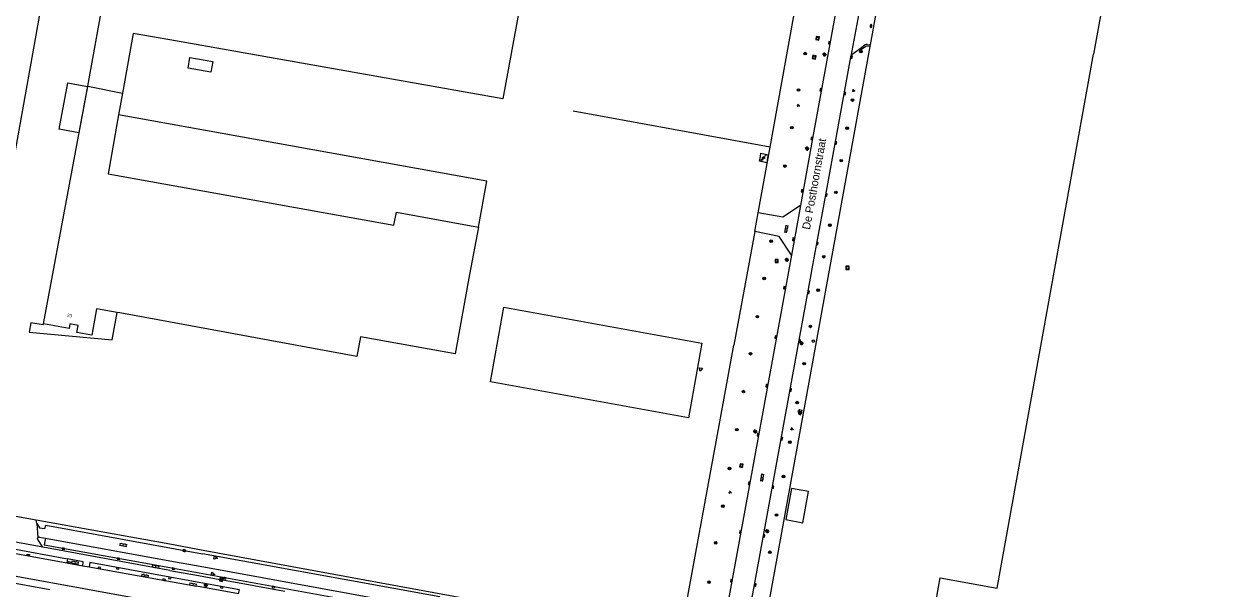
# Model space of a CAD drawing. Extents: x 130998 to 133001, y 398999 to 403002.
# Drawn here: x 131954.5 to 132332.6, y 399638.5 to 399814.9 of the extents above; entities that cross this region are included whole.
import ezdxf

# ---------------------------------------------------------------- set-up
doc = ezdxf.new("R2010")
doc.units = 0
for name, color, linetype in [('gg-afsc-hekwerk', 7, 'Continuous'), ('gg-anno-huisnummerreeks BGT', 7, 'Continuous'), ('gg-anno-openbare ruimte label', 7, 'Continuous'), ('gg-bbg-gedigitaliseerde bebouwing', 7, 'Continuous'), ('gg-bbg-gedigitaliseerde bijgebouw', 7, 'Continuous'), ('gg-bbg-hoofdgebouw', 7, 'Continuous'), ('gg-bbg-lage trafo', 7, 'Continuous'), ('gg-bbg-luifel en loopbrug', 7, 'Continuous'), ('gg-bbg-tussenscheiding', 7, 'Continuous'), ('gg-knt-verharding', 7, 'Continuous'), ('gg-knt-verharding nz', 7, 'Continuous'), ('gt-grn-weggrens', 7, 'Continuous'), ('gt-symb-boom', 7, 'Continuous'), ('gt-symb-brandkraan', 7, 'Continuous'), ('gt-symb-groenvak', 7, 'Continuous'), ('gt-symb-klinker verharding', 7, 'Continuous'), ('gt-symb-kolk', 7, 'Continuous'), ('gt-symb-kolk center center', 7, 'Continuous'), ('gt-symb-lichtmast', 7, 'Continuous'), ('gt-symb-rioolschacht', 7, 'Continuous'), ('gt-symb-trafo symbool', 7, 'Continuous'), ('gt-symb-waterafsluiter', 7, 'Continuous')]:
    doc.layers.add(name, color=color, linetype=linetype)

# ---------------------------------------------------------------- blocks, each defined once
blk = doc.blocks.new('gt0-BR')
at = {"layer": 'gt-symb-brandkraan'}
for centre, radius, start, end in [((-0.24, 0), 0.206, 107.5669, 252.4331), ((0.6, -2.66), 3, 106.892, 107.5669), ((0, -0.69), 0.938, 73.108, 106.892), ((-0.6, -2.66), 3, 72.4331, 73.108), ((0.24, 0), 0.206, 287.567, 72.4331), ((0.6, 2.66), 3, 252.4331, 253.108), ((0, 0.69), 0.938, 253.108, 286.8921), ((-0.6, 2.66), 3, 286.8921, 287.567)]:
    blk.add_arc(centre, radius, start, end, dxfattribs=at)
blk = doc.blocks.new('gt0-RS')
at = {"layer": 'gt-symb-rioolschacht'}
blk.add_lwpolyline([(-0.5, -0.5), (0.5, -0.5), (0.5, 0.5), (-0.5, 0.5)], close=True, dxfattribs=at)
blk.add_circle((0, 0), 0.375, dxfattribs=at)
blk = doc.blocks.new('gt0-BOOM')
at = {"layer": 'gt-symb-boom'}
for radius in [0.4, 0.2]:
    blk.add_circle((0, 0), radius, dxfattribs=at)
blk = doc.blocks.new('gt0-KOLK')
at = {"layer": 'gt-symb-kolk'}
blk.add_lwpolyline([(0, 0), (0.37, 0), (0.37, 0.4), (-0.38, 0.4), (-0.38, 0), (0, 0)], dxfattribs=at)
blk = doc.blocks.new('gt0-GRVAK')
at = {"layer": 'gt-symb-groenvak'}
for p, q in [((-0.11, 0.19), (-0.23, 0.24)), ((-0.18, 0.15), (0.09, 0.15)), ((-0.09, 0.21), (-0.16, 0.32)), ((-0.05, 0.21), (-0.05, 0.39)), ((0, 0.21), (0.06, 0.32)), ((0.01, 0.19), (0.13, 0.24)), ((0.26, -0.05), (0.2, 0.06)), ((0.3, -0.05), (0.3, 0.13)), ((0.35, -0.05), (0.41, 0.06)), ((-0.24, -0.23), (-0.36, -0.18)), ((-0.32, -0.26), (-0.05, -0.26)), ((-0.23, -0.21), (-0.29, -0.09)), ((-0.18, -0.2), (-0.18, -0.02)), ((-0.14, -0.21), (-0.07, -0.09)), ((-0.12, -0.23), (0, -0.18)), ((0.24, -0.07), (0.12, -0.02)), ((0.17, -0.11), (0.44, -0.11)), ((0.37, -0.07), (0.49, -0.02))]:
    blk.add_line(p, q, dxfattribs=at)
blk = doc.blocks.new('gt0-LMAST')
at = {"layer": 'gt-symb-lichtmast'}
for p, q in [((-0.18, 0.17), (-0.45, 0.44)), ((-0.01, 0.25), (-0.01, 0.62)), ((0.17, 0.17), (0.44, 0.44)), ((-0.26, 0), (-0.63, 0)), ((-0.18, -0.18), (-0.45, -0.45)), ((-0.01, -0.25), (-0.01, -0.63)), ((0.44, -0.45), (0.17, -0.18)), ((0.24, 0), (0.62, 0))]:
    blk.add_line(p, q, dxfattribs=at)
blk.add_circle((-0.01, 0), 0.25, dxfattribs=at)
blk = doc.blocks.new('gt0-KL1')
at = {"layer": 'gt-symb-klinker verharding'}
for p, q in [((-1.15, 0.3), (1.15, 0.3)), ((-1, -0.3), (-1, 0.3)), ((-0.5, 0.3), (-0.5, 0.45)), ((0, -0.3), (0, 0.3)), ((0.5, 0.3), (0.5, 0.45)), ((1, -0.3), (1, 0.3)), ((-1.15, -0.3), (1.15, -0.3)), ((-0.5, -0.45), (-0.5, -0.3)), ((0.5, -0.45), (0.5, -0.3))]:
    blk.add_line(p, q, dxfattribs=at)
blk = doc.blocks.new('gt0-HSP')
at = {"layer": 'gt-symb-trafo symbool'}
for points in [[(0.77, 0.75), (-0.53, 0), (0.47, 0), (-0.83, -0.75)], [(-0.22, -0.24), (-0.83, -0.75), (-0.08, -0.48)]]:
    blk.add_lwpolyline(points, dxfattribs=at)
blk = doc.blocks.new('gt0-WAFSL')
at = {"layer": 'gt-symb-waterafsluiter'}
for p, q in [((-0.5, -0.33), (0, 0.67)), ((0, 0.67), (0.5, -0.33)), ((0.5, -0.33), (-0.5, -0.33))]:
    blk.add_line(p, q, dxfattribs=at)
blk = doc.blocks.new('gt0-KOLKCC')
at = {"layer": 'gt-symb-kolk center center'}
blk.add_lwpolyline([(-0.38, 0.2), (0.38, 0.2), (0.38, -0.2), (-0.38, -0.2)], close=True, dxfattribs=at)

msp = doc.modelspace()

# ---------------------------------------------------------------- linework, layer by layer
at = {"layer": 'gg-afsc-hekwerk'}
for p, q in [((132187.47, 399776.47), (132196.35, 399825.7)), ((132220.46, 399818.27), (132218.65, 399808.43)), ((132218.65, 399808.43), (132218.55, 399807.89)), ((132187.47, 399776.47), (132125.97, 399787.71)), ((132183.73, 399756.01), (132187.47, 399776.47)), ((132182.65, 399750.15), (132183.73, 399756.01)), ((132182.65, 399750.15), (132176.15, 399714.67)), ((131958.19, 399660.02), (131943.8, 399662.62)), ((132000, 399652.44), (131958.19, 399660.02)), ((132010.38, 399650.54), (132000, 399652.44)), ((132159.36, 399623.22), (132010.38, 399650.54))]:
    msp.add_line(p, q, dxfattribs=at)
for points in [[(132218.55, 399807.89), (132187.28, 399635.5), (132187.07, 399633.45), (132186.62, 399631.09)], [(132159.36, 399623.22), (132171.78, 399690.65), (132176.15, 399714.67)]]:
    msp.add_lwpolyline(points, dxfattribs=at)
at = {"layer": 'gg-bbg-gedigitaliseerde bebouwing'}
for p, q in [((131974.33, 399795.51), (131987.77, 399870.1)), ((131960.49, 399721.28), (131974.33, 399795.51)), ((131985.19, 399793.41), (131983.98, 399786.64)), ((132096.35, 399751.54), (132093.54, 399736.72)), ((132093.54, 399736.72), (132089.03, 399711.94))]:
    msp.add_line(p, q, dxfattribs=at)
for points in [[(132114.18, 399847.19), (132103.99, 399791.64), (132000, 399810.02)], [(132000, 399810.02), (131988.52, 399812.05), (131985.19, 399793.41)], [(131983.98, 399786.64), (131980.67, 399768.12), (132069.97, 399752.08)], [(132069.97, 399752.08), (132070.78, 399756.15), (132096.35, 399751.54)]]:
    msp.add_lwpolyline(points, dxfattribs=at)
at = {"layer": 'gg-bbg-gedigitaliseerde bijgebouw'}
msp.add_lwpolyline([(132012.79, 399799.93), (132005.68, 399801.19), (132006.26, 399804.5), (132013.38, 399803.25), (132012.79, 399799.93)], dxfattribs=at)
at = {"layer": 'gg-bbg-hoofdgebouw'}
msp.add_line((131959.72, 399820.2), (131946.23, 399745.68), dxfattribs=at)
for points in [[(132454.05, 399775.54), (132469.16, 399858.93), (132303.58, 399888.86), (132288.47, 399805.5)], [(132454.05, 399775.54), (132418.41, 399578.69), (132399.92, 399582.07), (132402.13, 399594.22), (132402.06, 399594.24), (132402.06, 399594.26), (132250.49, 399621.7), (132250.45, 399621.52), (132249.94, 399621.63), (132249.86, 399621.77), (132237.31, 399623.98), (132240.58, 399641.99), (132258.31, 399638.73), (132288.47, 399805.5)], [(131983.49, 399724.86), (131977.08, 399726.04), (131975.62, 399717.77), (131970.96, 399718.6), (131971.36, 399720.82), (131968.76, 399721.28), (131968.51, 399719.86), (131960.49, 399721.28)], [(132089.03, 399711.94), (132059.49, 399717.29), (132058.35, 399711.11), (131984.32, 399724.71), (131983.49, 399724.86)], [(132166.16, 399715.24), (132161.91, 399691.91), (132100.06, 399703.16), (132104.31, 399726.49), (132166.16, 399715.24)]]:
    msp.add_lwpolyline(points, dxfattribs=at)
at = {"layer": 'gg-bbg-lage trafo'}
msp.add_lwpolyline([(132184.1, 399772.07), (132184.45, 399773.55), (132184.56, 399774.57), (132186.87, 399774.11), (132186.6, 399773.14), (132186.37, 399771.6), (132184.1, 399772.07)], dxfattribs=at)
at = {"layer": 'gg-bbg-luifel en loopbrug'}
for points in [[(131965.41, 399782.13), (131968.11, 399796.61), (131974.21, 399795.47), (131971.51, 399780.99), (131965.41, 399782.13)], [(132096.35, 399751.54), (132098.94, 399765.84), (131983.98, 399786.64)], [(131960.49, 399721.28), (131960.43, 399720.95), (131956.52, 399721.65), (131955.98, 399718.66), (131981.98, 399716.28), (131983.49, 399724.86)], [(132194.08, 399669.87), (132192.32, 399660.16), (132197.69, 399659.18), (132199.45, 399668.9), (132194.08, 399669.87)]]:
    msp.add_lwpolyline(points, dxfattribs=at)
at = {"layer": 'gg-bbg-tussenscheiding'}
msp.add_line((131974.33, 399795.51), (131985.19, 399793.41), dxfattribs=at)
at = {"layer": 'gg-knt-verharding'}
for p, q in [((132213.09, 399805.52), (132215.51, 399807.32)), ((132215.51, 399807.32), (132217, 399808.42)), ((132217.72, 399808.57), (132218.65, 399808.43)), ((132196.89, 399758.25), (132194.08, 399742.8)), ((132194.08, 399742.8), (132172.97, 399627)), ((131958.38, 399658.92), (131958.19, 399660.02)), ((131960.27, 399651.54), (131935.19, 399656.1)), ((131931.76, 399653.27), (131967.82, 399646.66)), ((131932.03, 399654.48), (131968.04, 399647.92)), ((131959.24, 399654.71), (131961.08, 399654.39)), ((132000, 399644.3), (131960.27, 399651.54)), ((131968.04, 399647.92), (131967.82, 399646.66)), ((131967.82, 399646.66), (131972.77, 399645.75)), ((131972.77, 399645.75), (131974.76, 399645.42)), ((131974.76, 399645.42), (132008.32, 399639.31)), ((132000, 399645.18), (132009.08, 399643.52)), ((132000, 399644.3), (132008.93, 399642.68)), ((132008.55, 399640.59), (132000, 399642.13)), ((132008.93, 399642.68), (132015.62, 399641.46)), ((132016.52, 399641.29), (132035.83, 399637.77)), ((132021.45, 399636.92), (132008.32, 399639.31))]:
    msp.add_line(p, q, dxfattribs=at)
for points in [[(132207.87, 399818.43), (132200.65, 399779.15), (132196.89, 399758.25)], [(132218.55, 399807.89), (132217.51, 399808.08), (132215.81, 399806.89), (132215.51, 399807.32)], [(132181.77, 399635.33), (132182.6, 399639.81), (132200.26, 399736.71), (132200.54, 399738.52), (132201.98, 399746.41), (132204.81, 399761.63), (132212.66, 399804.63), (132212.69, 399804.89)], [(132196.89, 399758.25), (132191.38, 399754.62), (132183.73, 399756.01)], [(132194.08, 399742.8), (132190.24, 399748.59), (132182.65, 399750.15)], [(131958.38, 399658.92), (131959.3, 399657.58), (131960.94, 399657.33), (131961.28, 399658.44), (132010.17, 399649.51)], [(131960.27, 399651.54), (131958.76, 399653.96), (131958.68, 399654.18), (131958.72, 399654.42)], [(131961.08, 399654.39), (131960.74, 399652.3), (132000, 399645.18)], [(131891.99, 399651.17), (131931.68, 399643.94), (131962.46, 399638.35)], [(131972.77, 399645.75), (131972.94, 399646.98), (131968.04, 399647.92)], [(132159.3, 399622.31), (132087.28, 399635.42), (132087.01, 399634.04), (132084.1, 399634.55), (132084.31, 399635.98), (132010.17, 399649.51)], [(132000, 399642.13), (131975.01, 399646.72), (131974.76, 399645.42)], [(132021.45, 399636.92), (132021.67, 399638.21), (132008.55, 399640.59)], [(132009.08, 399643.52), (132097.27, 399627.46), (132104.74, 399626.02), (132105.09, 399628.18)], [(132015.62, 399641.46), (132015.77, 399642.1), (132016.62, 399641.95), (132016.52, 399641.29)]]:
    msp.add_lwpolyline(points, dxfattribs=at)
for centre, radius, start, end in [((132217.49, 399807.86), 0.748, 72.0665, 131.1023), ((132213.69, 399804.7), 1.02, 126.1627, 169.1077), ((131959.17, 399654.22), 0.491, 81.6158, 156.735)]:
    msp.add_arc(centre, radius, start, end, dxfattribs=at)
at = {"layer": 'gg-knt-verharding nz'}
for p, q in [((132216.13, 399823.54), (132212.69, 399804.89)), ((132000, 399633.66), (131795.72, 399670.84)), ((131961.08, 399654.39), (132000, 399647.3)), ((132000, 399647.3), (132009.46, 399645.58)), ((132009.46, 399645.58), (132105.09, 399628.18))]:
    msp.add_line(p, q, dxfattribs=at)
at = {"layer": 'gt-grn-weggrens'}
for p, q in [((131958.38, 399658.92), (131958.72, 399654.42)), ((132015.62, 399641.46), (132016.52, 399641.29))]:
    msp.add_line(p, q, dxfattribs=at)

# ---------------------------------------------------------------- block references
at = {"layer": 'gt-symb-boom'}
for p in [(132215.8, 399806.36), (132198.38, 399805.72), (132196.32, 399794.34), (132213.17, 399791.21), (132194.22, 399782.57), (132211.51, 399782.43), (132209.66, 399772.26), (132192.02, 399770.59), (132207.99, 399762.39), (132206.07, 399752.15), (132187.76, 399747.14), (132204.19, 399742.27), (132185.56, 399735.47), (132202.45, 399731.84), (132183.46, 399723.54), (132200, 399720.51), (132181.3, 399711.96), (132198.05, 399708.88), (132179.1, 399700.14), (132195.9, 399696.71), (132177.05, 399688.26), (132193.6, 399684.34), (132174.75, 399676.14), (132191.64, 399673.61), (132172.65, 399664.36), (132189.44, 399661.58), (132170.44, 399652.89), (132187.33, 399649.96), (132168.34, 399640.62)]:
    msp.add_blockref('gt0-BOOM', p, dxfattribs=at)
at = {"layer": 'gt-symb-brandkraan'}
for p, rotation in [((132218.95, 399814.34), -100.6816207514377), ((132004.49, 399650.46), -12.06274602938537)]:
    msp.add_blockref('gt0-BR', p, dxfattribs=dict(at, rotation=rotation))
msp.add_blockref('gt0-BR', (132200.93, 399715.94), dxfattribs=at)
at = {"layer": 'gt-symb-groenvak'}
msp.add_blockref('gt0-GRVAK', (132213.46, 399794.2), dxfattribs=at)
for p, rotation in [((132196.24, 399789.54), -10.017934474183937), ((132194.24, 399688.48), -10.017934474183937), ((132174.9, 399668.71), -10.017934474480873)]:
    msp.add_blockref('gt0-GRVAK', p, dxfattribs=dict(at, rotation=rotation))
at = {"layer": 'gt-symb-klinker verharding'}
for p, rotation in [((132192.52, 399750.91), 79.28535610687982), ((132184.99, 399673.26), 79.69002960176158), ((131985.44, 399652.29), -10.366322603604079), ((131970.4, 399646.75), -10.074332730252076), ((131995.59, 399645.49), -10.48938981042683), ((131992.25, 399642.65), -10.422654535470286), ((132007.26, 399639.88), -10.140793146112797)]:
    msp.add_blockref('gt0-KL1', p, dxfattribs=dict(at, rotation=rotation))
at = {"layer": 'gt-symb-kolk'}
for p, rotation in [((132206.1, 399809.03), 78.92612884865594), ((132212.66, 399804.63), -100.30340299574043), ((132203.46, 399794.37), 79.63367739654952), ((132210.59, 399793.26), -100.34454247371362), ((132200.65, 399779.15), 79.51061018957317), ((132207.78, 399777.84), -100.3698076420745), ((132197.64, 399762.83), 79.39794170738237), ((132204.81, 399761.63), -100.5423203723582), ((132194.84, 399747.69), 79.51061018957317), ((132201.98, 399746.41), -100.32072607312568), ((132192.07, 399732.52), 79.63367739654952), ((132199.23, 399731.17), -100.43302473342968), ((132189.32, 399717.14), 79.925667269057), ((132196.43, 399715.98), -100.1407931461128), ((132186.55, 399701.96), 79.63367739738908), ((132193.69, 399700.68), -100.36632260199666), ((132183.85, 399686.66), 79.98206552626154), ((132190.9, 399685.45), -100.3663226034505), ((132181.09, 399671.44), 79.69002960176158), ((132188.12, 399670.3), -101.07387115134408), ((132178.3, 399656.2), 79.63367739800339), ((132185.33, 399655.09), -102.06274602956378), ((131966.79, 399651.23), 169.92566726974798), ((131983.96, 399648.11), 169.74640198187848), ((131968.51, 399646.53), -10.54573436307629), ((131977.91, 399644.84), -10.30997039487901), ((131983.77, 399645.11), 169.69002960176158), ((132001.09, 399644.98), 169.69002960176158), ((131998.11, 399641.17), -12.771242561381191), ((131999.98, 399642.13), 169.69002960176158), ((132017.19, 399642.05), 169.69002960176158), ((132175.52, 399641.02), 79.45426563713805), ((132182.6, 399639.81), -100.55025395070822), ((132016.19, 399639.19), 169.85920685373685), ((132032.41, 399639.27), 169.63367739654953)]:
    msp.add_blockref('gt0-KOLK', p, dxfattribs=dict(at, rotation=rotation))
at = {"layer": 'gt-symb-kolk center center', "rotation": -10.545734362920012}
msp.add_blockref('gt0-KOLKCC', (131955.74, 399649.08), dxfattribs=at)
at = {"layer": 'gt-symb-lichtmast'}
for p in [(132204.42, 399805.4), (132199.01, 399776.03), (132192.65, 399741.32), (132197.24, 399715.24), (132182.81, 399687.68), (132186.57, 399656.56), (132011.2, 399639.66)]:
    msp.add_blockref('gt0-LMAST', p, dxfattribs=at)
at = {"layer": 'gt-symb-rioolschacht'}
for p, rotation in [((132202.25, 399810.52), -100.1972055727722), ((132201.18, 399804.61), 78.7012997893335), ((132178.46, 399677.03), 79.69002960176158), ((132016.05, 399641.39), 75.51896562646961)]:
    msp.add_blockref('gt0-RS', p, dxfattribs=dict(at, rotation=rotation))
for p in [(132189.5, 399740.94), (132211.61, 399738.8)]:
    msp.add_blockref('gt0-RS', p, dxfattribs=at)
at = {"layer": 'gt-symb-trafo symbool'}
msp.add_blockref('gt0-HSP', (132185.39, 399773.12), dxfattribs=at)
at = {"layer": 'gt-symb-waterafsluiter'}
for p, rotation in [((132165.76, 399707.19), 169.4542656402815), ((132196.65, 399693.67), 169.45426563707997), ((132196.8, 399693.39), 169.4542656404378), ((132196.94, 399694.12), 169.45426563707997), ((132014.15, 399648.27), -100.30997039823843), ((132013.32, 399643.14), -100.30997039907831)]:
    msp.add_blockref('gt0-WAFSL', p, dxfattribs=dict(at, rotation=rotation))

# ---------------------------------------------------------------- texts
at = {"layer": 'gg-anno-huisnummerreeks BGT'}
msp.add_text('23', height=1, rotation=349.9, dxfattribs=at).set_placement((131967.8, 399723.54))
at = {"layer": 'gg-anno-openbare ruimte label'}
msp.add_text('De Posthoornstraat', height=2.5, rotation=79.8, dxfattribs=at).set_placement((132199.86, 399750.59))

doc.saveas('drawing.dxf')
